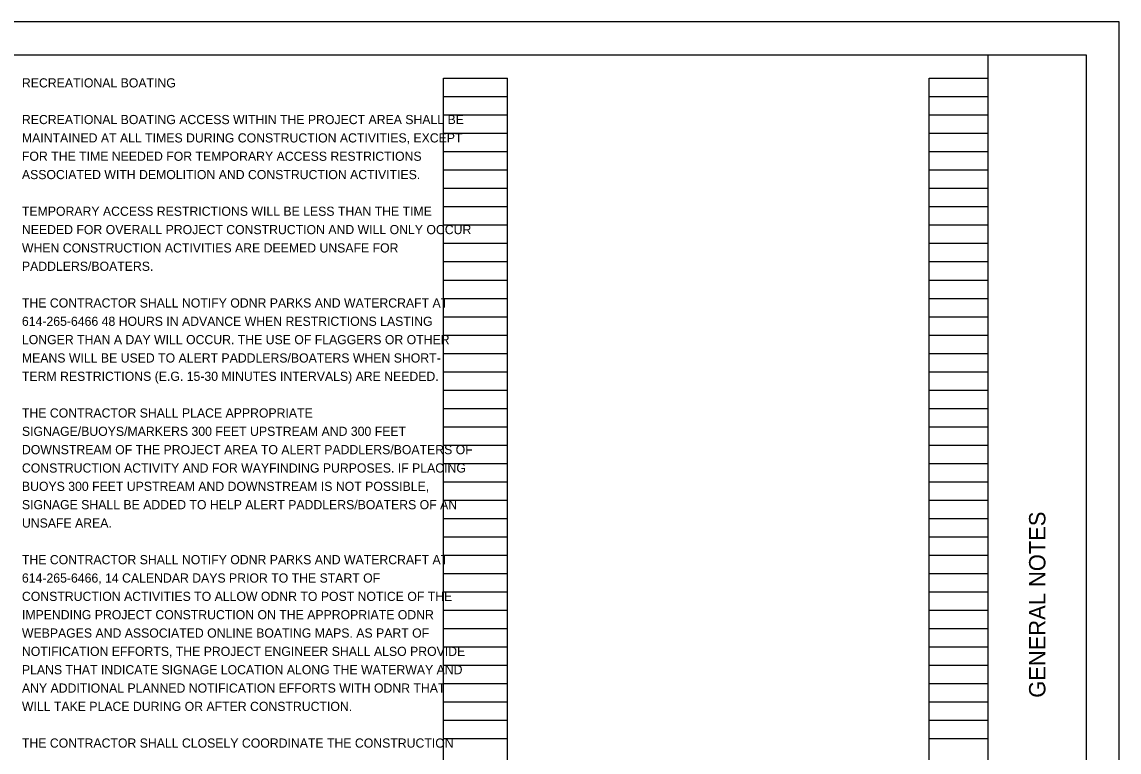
# Model space of a CAD drawing. Extents: x 0 to 34, y 0 to 22.
# Drawn here: x 17.24 to 34, y 10.85 to 22 of the extents above; entities that cross this region are included whole.
import ezdxf

# ---------------------------------------------------------------- set-up
doc = ezdxf.new("R2010")
doc.units = 0
for name, color, linetype in [('SH_Border', 7, 'Continuous'), ('SH_Cut_Line', 7, 'Continuous'), ('SH_Data', 7, 'Continuous'), ('SH_Text', 7, 'Continuous')]:
    doc.layers.add(name, color=color, linetype=linetype)

msp = doc.modelspace()

# ---------------------------------------------------------------- linework, layer by layer
at = {"layer": 'SH_Border'}
msp.add_line((32, 0.5), (32, 21.5), dxfattribs=at)
msp.add_lwpolyline([(1.5, 21.5), (33.5, 21.5), (33.5, 0.5), (1.5, 0.5)], close=True, dxfattribs=at)
at = {"layer": 'SH_Cut_Line'}
msp.add_lwpolyline([(0, 0), (34, 0), (34, 22), (0, 22)], close=True, dxfattribs=at)
at = {"layer": 'SH_Data'}
for p, q in [((23.68, 0.98), (23.68, 21.14)), ((23.68, 21.14), (24.66, 21.14)), ((24.66, 0.98), (24.66, 21.14)), ((31.1, 0.98), (31.1, 21.14)), ((31.1, 21.14), (32, 21.14)), ((32, 0.98), (32, 21.14)), ((23.68, 20.86), (24.66, 20.86)), ((31.1, 20.86), (32, 20.86)), ((23.68, 20.58), (24.66, 20.58)), ((31.1, 20.58), (32, 20.58)), ((23.68, 20.3), (24.66, 20.3)), ((31.1, 20.3), (32, 20.3)), ((23.68, 20.02), (24.66, 20.02)), ((31.1, 20.02), (32, 20.02)), ((23.68, 19.74), (24.66, 19.74)), ((31.1, 19.74), (32, 19.74)), ((23.68, 19.46), (24.66, 19.46)), ((31.1, 19.46), (32, 19.46)), ((23.68, 19.18), (24.66, 19.18)), ((31.1, 19.18), (32, 19.18)), ((23.68, 18.9), (24.66, 18.9)), ((31.1, 18.9), (32, 18.9)), ((23.68, 18.62), (24.66, 18.62)), ((31.1, 18.62), (32, 18.62)), ((23.68, 18.34), (24.66, 18.34)), ((31.1, 18.34), (32, 18.34)), ((23.68, 18.06), (24.66, 18.06)), ((31.1, 18.06), (32, 18.06)), ((23.68, 17.78), (24.66, 17.78)), ((31.1, 17.78), (32, 17.78)), ((23.68, 17.5), (24.66, 17.5)), ((31.1, 17.5), (32, 17.5)), ((23.68, 17.22), (24.66, 17.22)), ((31.1, 17.22), (32, 17.22)), ((23.68, 16.94), (24.66, 16.94)), ((31.1, 16.94), (32, 16.94)), ((23.68, 16.66), (24.66, 16.66)), ((31.1, 16.66), (32, 16.66)), ((23.68, 16.38), (24.66, 16.38)), ((31.1, 16.38), (32, 16.38)), ((23.68, 16.1), (24.66, 16.1)), ((31.1, 16.1), (32, 16.1)), ((23.68, 15.82), (24.66, 15.82)), ((31.1, 15.82), (32, 15.82)), ((23.68, 15.54), (24.66, 15.54)), ((31.1, 15.54), (32, 15.54)), ((23.68, 15.26), (24.66, 15.26)), ((31.1, 15.26), (32, 15.26)), ((23.68, 14.98), (24.66, 14.98)), ((31.1, 14.98), (32, 14.98)), ((23.68, 14.7), (24.66, 14.7)), ((31.1, 14.7), (32, 14.7)), ((23.68, 14.42), (24.66, 14.42)), ((31.1, 14.42), (32, 14.42)), ((23.68, 14.14), (24.66, 14.14)), ((31.1, 14.14), (32, 14.14)), ((23.68, 13.86), (24.66, 13.86)), ((31.1, 13.86), (32, 13.86)), ((23.68, 13.58), (24.66, 13.58)), ((31.1, 13.58), (32, 13.58)), ((23.68, 13.3), (24.66, 13.3)), ((31.1, 13.3), (32, 13.3)), ((23.68, 13.02), (24.66, 13.02)), ((31.1, 13.02), (32, 13.02)), ((23.68, 12.74), (24.66, 12.74)), ((31.1, 12.74), (32, 12.74)), ((23.68, 12.46), (24.66, 12.46)), ((31.1, 12.46), (32, 12.46)), ((23.68, 12.18), (24.66, 12.18)), ((31.1, 12.18), (32, 12.18)), ((23.68, 11.9), (24.66, 11.9)), ((31.1, 11.9), (32, 11.9)), ((23.68, 11.62), (24.66, 11.62)), ((31.1, 11.62), (32, 11.62)), ((23.68, 11.34), (24.66, 11.34)), ((31.1, 11.34), (32, 11.34)), ((23.68, 11.06), (24.66, 11.06)), ((31.1, 11.06), (32, 11.06))]:
    msp.add_line(p, q, dxfattribs=at)

# ---------------------------------------------------------------- texts
msp.add_text('GENERAL NOTES', height=0.25, rotation=90, dxfattribs=at).set_placement((32.875, 11.682))
at = {"layer": 'SH_Text'}
for s, p in [('RECREATIONAL BOATING ', (17.24, 21)), ('RECREATIONAL BOATING ACCESS WITHIN THE PROJECT AREA SHALL BE ', (17.24, 20.44)), ('MAINTAINED AT ALL TIMES DURING CONSTRUCTION ACTIVITIES, EXCEPT ', (17.24, 20.16)), ('FOR THE TIME NEEDED FOR TEMPORARY ACCESS RESTRICTIONS ', (17.24, 19.88)), ('ASSOCIATED WITH DEMOLITION AND CONSTRUCTION ACTIVITIES. ', (17.24, 19.6)), ('TEMPORARY ACCESS RESTRICTIONS WILL BE LESS THAN THE TIME ', (17.24, 19.04)), ('NEEDED FOR OVERALL PROJECT CONSTRUCTION AND WILL ONLY OCCUR ', (17.24, 18.76)), ('WHEN CONSTRUCTION ACTIVITIES ARE DEEMED UNSAFE FOR ', (17.24, 18.48)), ('PADDLERS/BOATERS.  ', (17.24, 18.2)), ('THE CONTRACTOR SHALL NOTIFY ODNR PARKS AND WATERCRAFT AT ', (17.24, 17.64)), ('614-265-6466 48 HOURS IN ADVANCE WHEN RESTRICTIONS LASTING ', (17.24, 17.36)), ('LONGER THAN A DAY WILL OCCUR. THE USE OF FLAGGERS OR OTHER ', (17.24, 17.08)), ('MEANS WILL BE USED TO ALERT PADDLERS/BOATERS WHEN SHORT-', (17.24, 16.8)), ('TERM RESTRICTIONS (E.G. 15-30 MINUTES INTERVALS) ARE NEEDED. ', (17.24, 16.52)), ('THE CONTRACTOR SHALL PLACE APPROPRIATE ', (17.24, 15.96)), ('SIGNAGE/BUOYS/MARKERS 300 FEET UPSTREAM AND 300 FEET ', (17.24, 15.68)), ('DOWNSTREAM OF THE PROJECT AREA TO ALERT PADDLERS/BOATERS OF ', (17.24, 15.4)), ('CONSTRUCTION ACTIVITY AND FOR WAYFINDING PURPOSES. IF PLACING ', (17.24, 15.12)), ('BUOYS 300 FEET UPSTREAM AND DOWNSTREAM IS NOT POSSIBLE, ', (17.24, 14.84)), ('SIGNAGE SHALL BE ADDED TO HELP ALERT PADDLERS/BOATERS OF AN ', (17.24, 14.56)), ('UNSAFE AREA.', (17.24, 14.28)), ('THE CONTRACTOR SHALL NOTIFY ODNR PARKS AND WATERCRAFT AT ', (17.24, 13.72)), ('614-265-6466, 14 CALENDAR DAYS PRIOR TO THE START OF ', (17.24, 13.44)), ('CONSTRUCTION ACTIVITIES TO ALLOW ODNR TO POST NOTICE OF THE ', (17.24, 13.16)), ('IMPENDING PROJECT CONSTRUCTION ON THE APPROPRIATE ODNR ', (17.24, 12.88)), ('WEBPAGES AND ASSOCIATED ONLINE BOATING MAPS. AS PART OF ', (17.24, 12.6)), ('NOTIFICATION EFFORTS, THE PROJECT ENGINEER SHALL ALSO PROVIDE ', (17.24, 12.32)), ('PLANS THAT INDICATE SIGNAGE LOCATION ALONG THE WATERWAY AND ', (17.24, 12.04)), ('ANY ADDITIONAL PLANNED NOTIFICATION EFFORTS WITH ODNR THAT ', (17.24, 11.76)), ('WILL TAKE PLACE DURING OR AFTER CONSTRUCTION.', (17.24, 11.48)), ('THE CONTRACTOR SHALL CLOSELY COORDINATE THE CONSTRUCTION ', (17.24, 10.92))]:
    msp.add_text(s, height=0.14, dxfattribs=at).set_placement(p)

doc.saveas('drawing.dxf')
